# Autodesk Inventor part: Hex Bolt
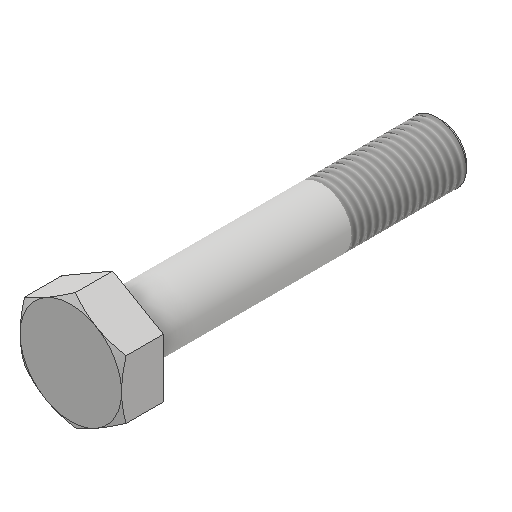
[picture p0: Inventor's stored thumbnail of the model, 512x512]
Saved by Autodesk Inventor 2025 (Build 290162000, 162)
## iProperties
Created: 2016-05
Part Number: Hex Bolt
Material: Generic
Document SubType Name: Modeling
Designer: CADCIM
Density: 1 g/cm^3
Appearance: Default
Author: CADCIM
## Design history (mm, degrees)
sketch "Sketch1"
  geometry: L1 (0, -19.63)-(-17, -9.815); L2 (-17, -9.815)-(-17, 9.815); L3 (-17, 9.815)-(0, 19.63); L4 (0, 19.63)-(17, 9.815); L5 (17, 9.815)-(17, -9.815); L6 (17, -9.815)-(0, -19.63); 2 further points
  constraints: 12 end point, 1 coincident, 13 other
  dimensions: "d0" = 34 distance between parallel lines of L2 L5
extrude "Extrusion1" new body sketch "Sketch1" distance "d1" = 14; taper "d2" = 0 deg
sketch "Sketch3"
  geometry: C1 r 10 at (0, 0); 1 further point
  constraints: 1 centre point, 1 coincident
  dimensions: "d3" = 20 diameter of C1
extrude "Extrusion2" join sketch "Sketch3" distance "d4" = 110; taper "d5" = 0 deg
thread "Thread1" dims "d6" = 40, "d7" = 0
sketch "Sketch4"
  geometry: L1 (0, -19.63)-(17, -9.815) reference; C1 r 17 at (0, 0); 1 further point
  constraints: 1 centre point, 1 coincident, 1 tangent
extrude "Extrusion3" sketch "Sketch4" distance "d8" = 200; taper "d9" = 60 deg
chamfer "Chamfer1" distance "d10" = 1.5; stored, may be unused: second distance "d11" = 2, angle "d12" = 45 deg
body "Solid1"
sketch "Sketch2"
  geometry: 1 further point
